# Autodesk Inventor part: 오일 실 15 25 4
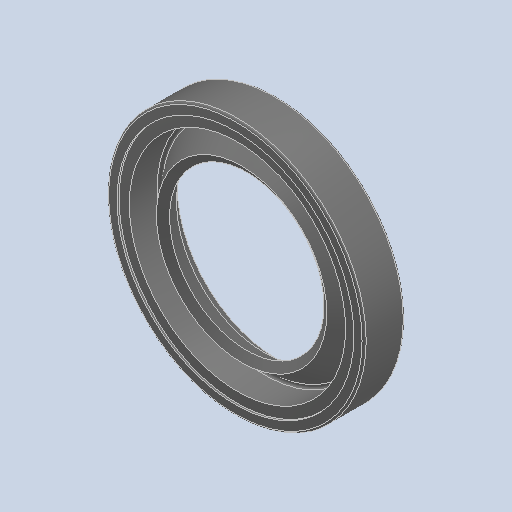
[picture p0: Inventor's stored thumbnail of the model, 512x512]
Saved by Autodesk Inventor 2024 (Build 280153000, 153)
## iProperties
Created: 2024-10
Part Number: 오일 실 15 25 4
Material: 고무
Description: 오일 실 - 비스프링, 조립 GA
Document SubType Name: Modeling
Designer: user
Density: 0.93 g/cm^3
Appearance: 기본값
Author: jhkim
Sending System: Autodesk Inventor 2025
Preprocessor: ST-DEVELOPER v20
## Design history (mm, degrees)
feature "Solid1"
node "솔리드1"
